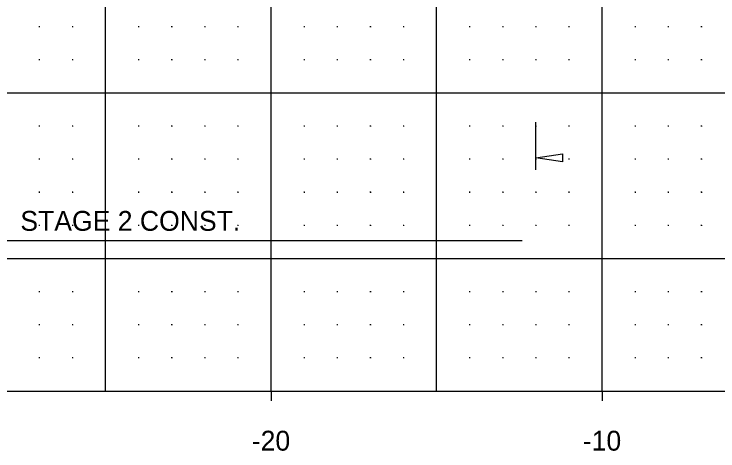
# Model space of a CAD drawing. Extents: x -80 to 80, y 222 to 253.
# Drawn here: x -27.76 to -6.5, y 224.19 to 237.38 of the extents above; entities that cross this region are included whole.
import ezdxf

# ---------------------------------------------------------------- set-up
doc = ezdxf.new("R2010")
doc.units = 0
for name, color, linetype in [('Default', 7, 'Continuous'), ('DSN_DRFT_XS Border Grid', 7, 'Continuous'), ('DSN_DRFT_XS Grid Annotations', 7, 'Continuous'), ('DSN_DRFT_XS Grid Major', 7, 'Continuous'), ('DSN_DRFT_XS Grid Minor', 7, 'Continuous'), ('DSN_DRFT_XS MOT STG Annotations', 7, 'Continuous')]:
    doc.layers.add(name, color=color, linetype=linetype)

msp = doc.modelspace()

# ---------------------------------------------------------------- linework, layer by layer
at = {"layer": 'DSN_DRFT_XS Border Grid'}
msp.add_line((-77.5, 226), (77.5, 226), dxfattribs=at)
at = {"layer": 'DSN_DRFT_XS Grid Major'}
for p, q in [((-25, 226), (-25, 250.573)), ((-20, 226), (-20, 250.573)), ((-15, 226), (-15, 250.573)), ((-10, 226), (-10, 250.573)), ((-77.5, 235), (77.5, 235)), ((-77.5, 230), (77.5, 230)), ((-20, 226), (-20, 225.7)), ((-10, 226), (-10, 225.7))]:
    msp.add_line(p, q, dxfattribs=at)
at = {"layer": 'DSN_DRFT_XS Grid Minor'}
for p, q in [((-26.988, 237), (-27.012, 237)), ((-27, 237.012), (-27, 236.988)), ((-25.988, 237), (-26.012, 237)), ((-26, 237.012), (-26, 236.988)), ((-23.988, 237), (-24.012, 237)), ((-24, 237.012), (-24, 236.988)), ((-22.988, 237), (-23.012, 237)), ((-23, 237.012), (-23, 236.988)), ((-21.988, 237), (-22.012, 237)), ((-22, 237.012), (-22, 236.988)), ((-20.988, 237), (-21.012, 237)), ((-21, 237.012), (-21, 236.988)), ((-18.988, 237), (-19.012, 237)), ((-19, 237.012), (-19, 236.988)), ((-17.988, 237), (-18.012, 237)), ((-18, 237.012), (-18, 236.988)), ((-16.988, 237), (-17.012, 237)), ((-17, 237.012), (-17, 236.988)), ((-15.988, 237), (-16.012, 237)), ((-16, 237.012), (-16, 236.988)), ((-13.988, 237), (-14.012, 237)), ((-14, 237.012), (-14, 236.988)), ((-12.988, 237), (-13.012, 237)), ((-13, 237.012), (-13, 236.988)), ((-11.988, 237), (-12.012, 237)), ((-12, 237.012), (-12, 236.988)), ((-10.988, 237), (-11.012, 237)), ((-11, 237.012), (-11, 236.988)), ((-8.988, 237), (-9.012, 237)), ((-9, 237.012), (-9, 236.988)), ((-7.988, 237), (-8.012, 237)), ((-8, 237.012), (-8, 236.988)), ((-6.988, 237), (-7.012, 237)), ((-7, 237.012), (-7, 236.988)), ((-26.988, 236), (-27.012, 236)), ((-27, 236.012), (-27, 235.988)), ((-25.988, 236), (-26.012, 236)), ((-26, 236.012), (-26, 235.988)), ((-23.988, 236), (-24.012, 236)), ((-24, 236.012), (-24, 235.988)), ((-22.988, 236), (-23.012, 236)), ((-23, 236.012), (-23, 235.988)), ((-21.988, 236), (-22.012, 236)), ((-22, 236.012), (-22, 235.988)), ((-20.988, 236), (-21.012, 236)), ((-21, 236.012), (-21, 235.988)), ((-18.988, 236), (-19.012, 236)), ((-19, 236.012), (-19, 235.988)), ((-17.988, 236), (-18.012, 236)), ((-18, 236.012), (-18, 235.988)), ((-16.988, 236), (-17.012, 236)), ((-17, 236.012), (-17, 235.988)), ((-15.988, 236), (-16.012, 236)), ((-16, 236.012), (-16, 235.988)), ((-13.988, 236), (-14.012, 236)), ((-14, 236.012), (-14, 235.988)), ((-12.988, 236), (-13.012, 236)), ((-13, 236.012), (-13, 235.988)), ((-11.988, 236), (-12.012, 236)), ((-12, 236.012), (-12, 235.988)), ((-10.988, 236), (-11.012, 236)), ((-11, 236.012), (-11, 235.988)), ((-8.988, 236), (-9.012, 236)), ((-9, 236.012), (-9, 235.988)), ((-7.988, 236), (-8.012, 236)), ((-8, 236.012), (-8, 235.988)), ((-6.988, 236), (-7.012, 236)), ((-7, 236.012), (-7, 235.988)), ((-26.988, 234), (-27.012, 234)), ((-27, 234.012), (-27, 233.988)), ((-25.988, 234), (-26.012, 234)), ((-26, 234.012), (-26, 233.988)), ((-23.988, 234), (-24.012, 234)), ((-24, 234.012), (-24, 233.988)), ((-22.988, 234), (-23.012, 234)), ((-23, 234.012), (-23, 233.988)), ((-21.988, 234), (-22.012, 234)), ((-22, 234.012), (-22, 233.988)), ((-20.988, 234), (-21.012, 234)), ((-21, 234.012), (-21, 233.988)), ((-18.988, 234), (-19.012, 234)), ((-19, 234.012), (-19, 233.988)), ((-17.988, 234), (-18.012, 234)), ((-18, 234.012), (-18, 233.988)), ((-16.988, 234), (-17.012, 234)), ((-17, 234.012), (-17, 233.988)), ((-15.988, 234), (-16.012, 234)), ((-16, 234.012), (-16, 233.988)), ((-13.988, 234), (-14.012, 234)), ((-14, 234.012), (-14, 233.988)), ((-12.988, 234), (-13.012, 234)), ((-13, 234.012), (-13, 233.988)), ((-11.988, 234), (-12.012, 234)), ((-12, 234.012), (-12, 233.988)), ((-10.988, 234), (-11.012, 234)), ((-11, 234.012), (-11, 233.988)), ((-8.988, 234), (-9.012, 234)), ((-9, 234.012), (-9, 233.988)), ((-7.988, 234), (-8.012, 234)), ((-8, 234.012), (-8, 233.988)), ((-6.988, 234), (-7.012, 234)), ((-7, 234.012), (-7, 233.988)), ((-26.988, 233), (-27.012, 233)), ((-27, 233.012), (-27, 232.988)), ((-25.988, 233), (-26.012, 233)), ((-26, 233.012), (-26, 232.988)), ((-23.988, 233), (-24.012, 233)), ((-24, 233.012), (-24, 232.988)), ((-22.988, 233), (-23.012, 233)), ((-23, 233.012), (-23, 232.988)), ((-21.988, 233), (-22.012, 233)), ((-22, 233.012), (-22, 232.988)), ((-20.988, 233), (-21.012, 233)), ((-21, 233.012), (-21, 232.988)), ((-18.988, 233), (-19.012, 233)), ((-19, 233.012), (-19, 232.988)), ((-17.988, 233), (-18.012, 233)), ((-18, 233.012), (-18, 232.988)), ((-16.988, 233), (-17.012, 233)), ((-17, 233.012), (-17, 232.988)), ((-15.988, 233), (-16.012, 233)), ((-16, 233.012), (-16, 232.988)), ((-13.988, 233), (-14.012, 233)), ((-14, 233.012), (-14, 232.988)), ((-12.988, 233), (-13.012, 233)), ((-13, 233.012), (-13, 232.988)), ((-11.988, 233), (-12.012, 233)), ((-12, 233.012), (-12, 232.988)), ((-10.988, 233), (-11.012, 233)), ((-11, 233.012), (-11, 232.988)), ((-8.988, 233), (-9.012, 233)), ((-9, 233.012), (-9, 232.988)), ((-7.988, 233), (-8.012, 233)), ((-8, 233.012), (-8, 232.988)), ((-6.988, 233), (-7.012, 233)), ((-7, 233.012), (-7, 232.988)), ((-26.988, 232), (-27.012, 232)), ((-27, 232.012), (-27, 231.988)), ((-25.988, 232), (-26.012, 232)), ((-26, 232.012), (-26, 231.988)), ((-23.988, 232), (-24.012, 232)), ((-24, 232.012), (-24, 231.988)), ((-22.988, 232), (-23.012, 232)), ((-23, 232.012), (-23, 231.988)), ((-21.988, 232), (-22.012, 232)), ((-22, 232.012), (-22, 231.988)), ((-20.988, 232), (-21.012, 232)), ((-21, 232.012), (-21, 231.988)), ((-18.988, 232), (-19.012, 232)), ((-19, 232.012), (-19, 231.988)), ((-17.988, 232), (-18.012, 232)), ((-18, 232.012), (-18, 231.988)), ((-16.988, 232), (-17.012, 232)), ((-17, 232.012), (-17, 231.988)), ((-15.988, 232), (-16.012, 232)), ((-16, 232.012), (-16, 231.988)), ((-13.988, 232), (-14.012, 232)), ((-14, 232.012), (-14, 231.988)), ((-12.988, 232), (-13.012, 232)), ((-13, 232.012), (-13, 231.988)), ((-11.988, 232), (-12.012, 232)), ((-12, 232.012), (-12, 231.988)), ((-10.988, 232), (-11.012, 232)), ((-11, 232.012), (-11, 231.988)), ((-8.988, 232), (-9.012, 232)), ((-9, 232.012), (-9, 231.988)), ((-7.988, 232), (-8.012, 232)), ((-8, 232.012), (-8, 231.988)), ((-6.988, 232), (-7.012, 232)), ((-7, 232.012), (-7, 231.988)), ((-26.988, 231), (-27.012, 231)), ((-27, 231.012), (-27, 230.988)), ((-25.988, 231), (-26.012, 231)), ((-26, 231.012), (-26, 230.988)), ((-23.988, 231), (-24.012, 231)), ((-24, 231.012), (-24, 230.988)), ((-22.988, 231), (-23.012, 231)), ((-23, 231.012), (-23, 230.988)), ((-21.988, 231), (-22.012, 231)), ((-22, 231.012), (-22, 230.988)), ((-20.988, 231), (-21.012, 231)), ((-21, 231.012), (-21, 230.988)), ((-18.988, 231), (-19.012, 231)), ((-19, 231.012), (-19, 230.988)), ((-17.988, 231), (-18.012, 231)), ((-18, 231.012), (-18, 230.988)), ((-16.988, 231), (-17.012, 231)), ((-17, 231.012), (-17, 230.988)), ((-15.988, 231), (-16.012, 231)), ((-16, 231.012), (-16, 230.988)), ((-13.988, 231), (-14.012, 231)), ((-14, 231.012), (-14, 230.988)), ((-12.988, 231), (-13.012, 231)), ((-13, 231.012), (-13, 230.988)), ((-11.988, 231), (-12.012, 231)), ((-12, 231.012), (-12, 230.988)), ((-10.988, 231), (-11.012, 231)), ((-11, 231.012), (-11, 230.988)), ((-8.988, 231), (-9.012, 231)), ((-9, 231.012), (-9, 230.988)), ((-7.988, 231), (-8.012, 231)), ((-8, 231.012), (-8, 230.988)), ((-6.988, 231), (-7.012, 231)), ((-7, 231.012), (-7, 230.988)), ((-26.988, 229), (-27.012, 229)), ((-27, 229.012), (-27, 228.988)), ((-25.988, 229), (-26.012, 229)), ((-26, 229.012), (-26, 228.988)), ((-23.988, 229), (-24.012, 229)), ((-24, 229.012), (-24, 228.988)), ((-22.988, 229), (-23.012, 229)), ((-23, 229.012), (-23, 228.988)), ((-21.988, 229), (-22.012, 229)), ((-22, 229.012), (-22, 228.988)), ((-20.988, 229), (-21.012, 229)), ((-21, 229.012), (-21, 228.988)), ((-18.988, 229), (-19.012, 229)), ((-19, 229.012), (-19, 228.988)), ((-17.988, 229), (-18.012, 229)), ((-18, 229.012), (-18, 228.988)), ((-16.988, 229), (-17.012, 229)), ((-17, 229.012), (-17, 228.988)), ((-15.988, 229), (-16.012, 229)), ((-16, 229.012), (-16, 228.988)), ((-13.988, 229), (-14.012, 229)), ((-14, 229.012), (-14, 228.988)), ((-12.988, 229), (-13.012, 229)), ((-13, 229.012), (-13, 228.988)), ((-11.988, 229), (-12.012, 229)), ((-12, 229.012), (-12, 228.988)), ((-10.988, 229), (-11.012, 229)), ((-11, 229.012), (-11, 228.988)), ((-8.988, 229), (-9.012, 229)), ((-9, 229.012), (-9, 228.988)), ((-7.988, 229), (-8.012, 229)), ((-8, 229.012), (-8, 228.988)), ((-6.988, 229), (-7.012, 229)), ((-7, 229.012), (-7, 228.988)), ((-26.988, 228), (-27.012, 228)), ((-27, 228.012), (-27, 227.988)), ((-25.988, 228), (-26.012, 228)), ((-26, 228.012), (-26, 227.988)), ((-23.988, 228), (-24.012, 228)), ((-24, 228.012), (-24, 227.988)), ((-22.988, 228), (-23.012, 228)), ((-23, 228.012), (-23, 227.988)), ((-21.988, 228), (-22.012, 228)), ((-22, 228.012), (-22, 227.988)), ((-20.988, 228), (-21.012, 228)), ((-21, 228.012), (-21, 227.988)), ((-18.988, 228), (-19.012, 228)), ((-19, 228.012), (-19, 227.988)), ((-17.988, 228), (-18.012, 228)), ((-18, 228.012), (-18, 227.988)), ((-16.988, 228), (-17.012, 228)), ((-17, 228.012), (-17, 227.988)), ((-15.988, 228), (-16.012, 228)), ((-16, 228.012), (-16, 227.988)), ((-13.988, 228), (-14.012, 228)), ((-14, 228.012), (-14, 227.988)), ((-12.988, 228), (-13.012, 228)), ((-13, 228.012), (-13, 227.988)), ((-11.988, 228), (-12.012, 228)), ((-12, 228.012), (-12, 227.988)), ((-10.988, 228), (-11.012, 228)), ((-11, 228.012), (-11, 227.988)), ((-8.988, 228), (-9.012, 228)), ((-9, 228.012), (-9, 227.988)), ((-7.988, 228), (-8.012, 228)), ((-8, 228.012), (-8, 227.988)), ((-6.988, 228), (-7.012, 228)), ((-7, 228.012), (-7, 227.988)), ((-26.988, 227), (-27.012, 227)), ((-27, 227.012), (-27, 226.988)), ((-25.988, 227), (-26.012, 227)), ((-26, 227.012), (-26, 226.988)), ((-23.988, 227), (-24.012, 227)), ((-24, 227.012), (-24, 226.988)), ((-22.988, 227), (-23.012, 227)), ((-23, 227.012), (-23, 226.988)), ((-21.988, 227), (-22.012, 227)), ((-22, 227.012), (-22, 226.988)), ((-20.988, 227), (-21.012, 227)), ((-21, 227.012), (-21, 226.988)), ((-18.988, 227), (-19.012, 227)), ((-19, 227.012), (-19, 226.988)), ((-17.988, 227), (-18.012, 227)), ((-18, 227.012), (-18, 226.988)), ((-16.988, 227), (-17.012, 227)), ((-17, 227.012), (-17, 226.988)), ((-15.988, 227), (-16.012, 227)), ((-16, 227.012), (-16, 226.988)), ((-13.988, 227), (-14.012, 227)), ((-14, 227.012), (-14, 226.988)), ((-12.988, 227), (-13.012, 227)), ((-13, 227.012), (-13, 226.988)), ((-11.988, 227), (-12.012, 227)), ((-12, 227.012), (-12, 226.988)), ((-10.988, 227), (-11.012, 227)), ((-11, 227.012), (-11, 226.988)), ((-8.988, 227), (-9.012, 227)), ((-9, 227.012), (-9, 226.988)), ((-7.988, 227), (-8.012, 227)), ((-8, 227.012), (-8, 226.988)), ((-6.988, 227), (-7.012, 227)), ((-7, 227.012), (-7, 226.988))]:
    msp.add_line(p, q, dxfattribs=at)
at = {"layer": 'DSN_DRFT_XS MOT STG Annotations'}
for p, q in [((-12, 232.678), (-12, 234.118)), ((-44.67, 230.544), (-12.416, 230.544))]:
    msp.add_line(p, q, dxfattribs=at)
msp.add_lwpolyline([(-11.2, 232.918), (-12, 233.038), (-11.2, 233.158)], close=True, dxfattribs=at)

# ---------------------------------------------------------------- texts
at = {"layer": 'Default'}
msp.add_text('STAGE 2 CONST.', height=0.6, dxfattribs=at).set_placement((-27.573, 230.838))
at = {"layer": 'DSN_DRFT_XS Grid Annotations'}
for s, p in [('-20', (-20.581, 224.2)), ('-10', (-10.581, 224.2))]:
    msp.add_text(s, height=0.6, dxfattribs=at).set_placement(p)

doc.saveas('drawing.dxf')
